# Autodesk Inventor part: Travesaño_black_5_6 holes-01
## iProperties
Created: 2008-01
Part Number: Travesaño_black_5_6 holes-01
Material: Default
Document SubType Name: Modeling
Designer: eruiz-tagle
Mass: 1.07259 g
Surface Area: 20.3811 cm^2
Volume: 1.07259 cm^3
Density: 1 g/cm^3
Author: eruiz-tagle
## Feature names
1. Derived Body1 [Tagging]
